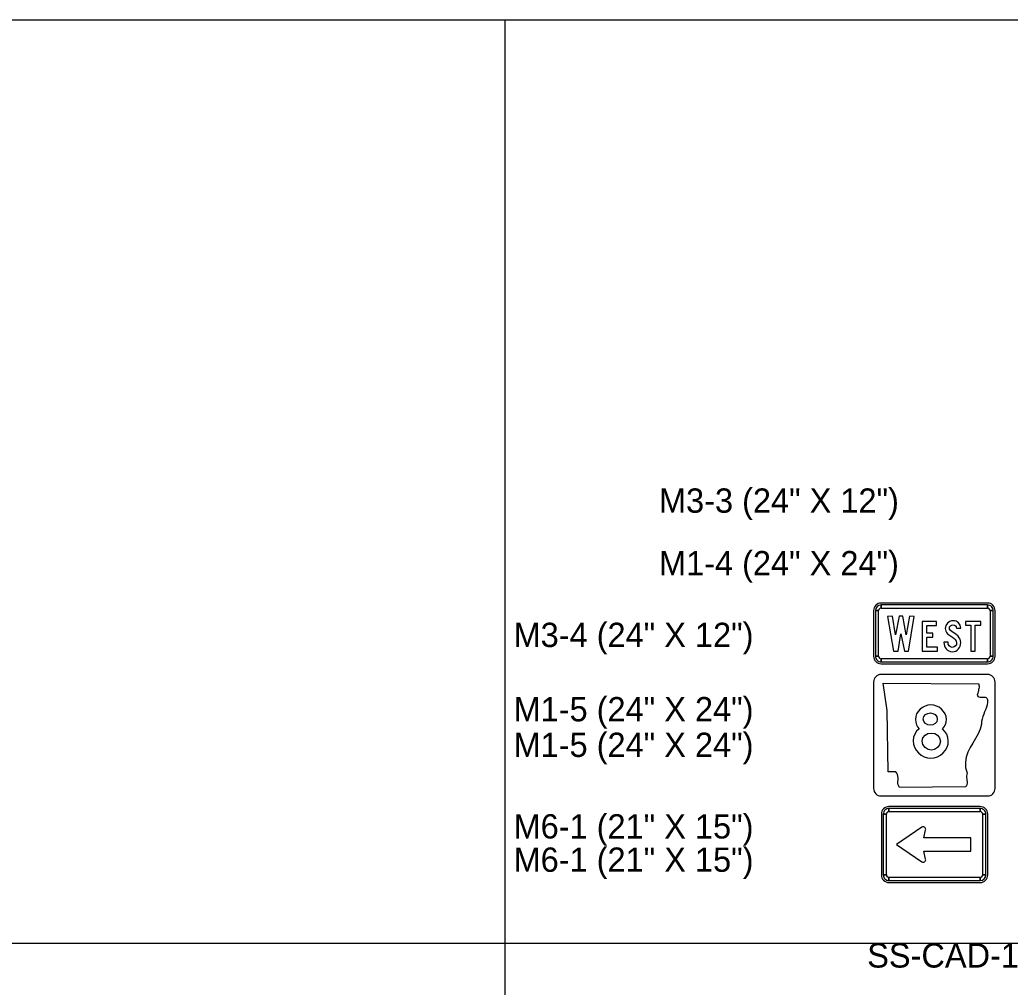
# Model space of a CAD drawing. Extents: x 1001568 to 1002149, y 1840825 to 1841423.
# Drawn here: x 1001912.67 to 1001928.96, y 1841194.75 to 1841210.67 of the extents above; entities that cross this region are included whole.
import ezdxf

# ---------------------------------------------------------------- set-up
doc = ezdxf.new("R2010")
doc.units = 0
for name, color, linetype in [('40', 7, 'Continuous'), ('R_No Plot', 7, 'Continuous'), ('SIGNS', 7, 'Continuous')]:
    doc.layers.add(name, color=color, linetype=linetype)

msp = doc.modelspace()

# ---------------------------------------------------------------- linework, layer by layer
at = {"layer": 'R_No Plot'}
for p, q in [((1001920.65, 1841210.667), (1001920.65, 1841148.127)), ((1001886.411, 1841195.469), (1001982.133, 1841195.469))]:
    msp.add_line(p, q, dxfattribs=at)
msp.add_lwpolyline([(1001886.411, 1841210.667), (1001964.232, 1841210.667), (1001964.232, 1841207.694), (1001968.454, 1841207.694), (1001968.454, 1841206.882), (1001982.133, 1841206.882), (1001982.133, 1841148.127), (1001886.411, 1841148.127)], close=True, dxfattribs=at)
at = {"layer": 'SIGNS'}
for p, q in [((1001928.589, 1841201.068), (1001926.839, 1841201.068)), ((1001926.839, 1841200.985), (1001926.839, 1841201.037)), ((1001928.589, 1841201.037), (1001928.589, 1841200.985)), ((1001926.714, 1841200.943), (1001926.714, 1841200.193)), ((1001926.745, 1841200.943), (1001926.797, 1841200.943)), ((1001928.631, 1841200.943), (1001928.683, 1841200.943)), ((1001928.714, 1841200.193), (1001928.714, 1841200.943)), ((1001926.797, 1841200.193), (1001926.745, 1841200.193)), ((1001928.683, 1841200.193), (1001928.631, 1841200.193)), ((1001926.839, 1841200.1), (1001926.839, 1841200.152)), ((1001926.839, 1841200.068), (1001928.589, 1841200.068)), ((1001928.589, 1841200.152), (1001928.589, 1841200.1)), ((1001928.589, 1841199.893), (1001926.839, 1841199.893)), ((1001926.714, 1841199.768), (1001926.714, 1841198.018)), ((1001928.714, 1841198.018), (1001928.714, 1841199.768)), ((1001926.714, 1841198.018), (1001926.714, 1841198.018)), ((1001926.839, 1841197.893), (1001928.589, 1841197.893)), ((1001926.843, 1841197.594), (1001926.843, 1841196.594)), ((1001926.874, 1841197.594), (1001926.926, 1841197.594)), ((1001928.468, 1841197.719), (1001926.968, 1841197.719)), ((1001926.968, 1841197.636), (1001926.968, 1841197.688)), ((1001928.468, 1841197.688), (1001928.468, 1841197.636)), ((1001928.509, 1841197.594), (1001928.562, 1841197.594)), ((1001928.593, 1841196.594), (1001928.593, 1841197.594)), ((1001927.508, 1841197.379), (1001927.093, 1841197.094)), ((1001927.541, 1841197.203), (1001927.571, 1841197.335)), ((1001928.312, 1841197.203), (1001927.541, 1841197.203)), ((1001928.312, 1841197.203), (1001928.312, 1841197.203)), ((1001928.312, 1841196.985), (1001928.312, 1841197.203)), ((1001927.093, 1841197.094), (1001927.093, 1841197.094)), ((1001927.093, 1841197.094), (1001927.508, 1841196.809)), ((1001927.571, 1841196.853), (1001927.541, 1841196.985)), ((1001927.541, 1841196.985), (1001928.312, 1841196.985)), ((1001926.926, 1841196.594), (1001926.874, 1841196.594)), ((1001926.968, 1841196.5), (1001926.968, 1841196.552)), ((1001926.968, 1841196.469), (1001928.468, 1841196.469)), ((1001928.468, 1841196.552), (1001928.468, 1841196.5)), ((1001928.562, 1841196.594), (1001928.509, 1841196.594))]:
    msp.add_line(p, q, dxfattribs=at)
for points in [[(1001928.589, 1841201.037), (1001926.839, 1841201.037), (1001926.839, 1841200.985), (1001928.589, 1841200.985), (1001928.589, 1841201.037), (1001928.589, 1841201.037)], [(1001926.745, 1841200.943), (1001926.745, 1841200.193), (1001926.797, 1841200.193), (1001926.797, 1841200.943), (1001926.745, 1841200.943), (1001926.745, 1841200.943)], [(1001927.041, 1841200.277), (1001927.118, 1841200.277), (1001927.164, 1841200.562), (1001927.221, 1841200.277), (1001927.291, 1841200.277), (1001927.384, 1841200.849), (1001927.304, 1841200.854), (1001927.253, 1841200.546), (1001927.197, 1841200.854), (1001927.133, 1841200.854), (1001927.076, 1841200.546), (1001927.027, 1841200.854), (1001926.946, 1841200.849)], [(1001928.683, 1841200.193), (1001928.683, 1841200.943), (1001928.631, 1841200.943), (1001928.631, 1841200.193), (1001928.683, 1841200.193), (1001928.683, 1841200.193)], [(1001927.768, 1841200.344), (1001927.588, 1841200.344), (1001927.588, 1841200.508), (1001927.69, 1841200.508), (1001927.69, 1841200.575), (1001927.588, 1841200.575), (1001927.588, 1841200.7), (1001927.75, 1841200.7), (1001927.75, 1841200.767), (1001927.516, 1841200.767), (1001927.516, 1841200.277), (1001927.768, 1841200.277)], [(1001927.872, 1841200.424), (1001927.872, 1841200.42), (1001927.874, 1841200.39), (1001927.881, 1841200.362), (1001927.893, 1841200.337), (1001927.91, 1841200.314), (1001927.931, 1841200.293), (1001927.955, 1841200.279), (1001927.981, 1841200.27), (1001928.01, 1841200.267), (1001928.04, 1841200.27), (1001928.066, 1841200.278), (1001928.09, 1841200.292), (1001928.111, 1841200.312), (1001928.127, 1841200.335), (1001928.139, 1841200.36), (1001928.146, 1841200.387), (1001928.148, 1841200.417), (1001928.146, 1841200.445), (1001928.137, 1841200.472), (1001928.123, 1841200.498), (1001928.104, 1841200.522), (1001928.067, 1841200.554), (1001928.01, 1841200.593), (1001927.973, 1841200.621), (1001927.965, 1841200.636), (1001927.962, 1841200.652), (1001927.966, 1841200.674), (1001927.98, 1841200.692), (1001927.999, 1841200.705), (1001928.021, 1841200.709), (1001928.046, 1841200.705), (1001928.063, 1841200.693), (1001928.073, 1841200.677), (1001928.08, 1841200.652), (1001928.148, 1841200.652), (1001928.137, 1841200.702), (1001928.111, 1841200.741), (1001928.092, 1841200.757), (1001928.071, 1841200.768), (1001928.046, 1841200.775), (1001928.019, 1841200.777), (1001927.994, 1841200.774), (1001927.971, 1841200.767), (1001927.95, 1841200.755), (1001927.931, 1841200.739), (1001927.903, 1841200.698), (1001927.894, 1841200.65), (1001927.896, 1841200.625), (1001927.903, 1841200.603), (1001927.915, 1841200.582), (1001927.931, 1841200.563), (1001928.011, 1841200.506), (1001928.041, 1841200.484), (1001928.059, 1841200.467), (1001928.075, 1841200.442), (1001928.081, 1841200.416), (1001928.076, 1841200.387), (1001928.062, 1841200.363), (1001928.039, 1841200.345), (1001928.01, 1841200.339), (1001927.98, 1841200.345), (1001927.957, 1841200.365), (1001927.943, 1841200.392), (1001927.939, 1841200.424)], [(1001928.316, 1841200.277), (1001928.388, 1841200.277), (1001928.388, 1841200.706), (1001928.479, 1841200.706), (1001928.479, 1841200.767), (1001928.227, 1841200.767), (1001928.227, 1841200.706), (1001928.316, 1841200.706)], [(1001926.839, 1841200.1), (1001928.589, 1841200.1), (1001928.589, 1841200.152), (1001926.839, 1841200.152), (1001926.839, 1841200.1), (1001926.839, 1841200.1)], [(1001928.444, 1841199.738), (1001928.448, 1841199.719), (1001928.45, 1841199.7), (1001928.449, 1841199.681), (1001928.447, 1841199.662), (1001928.443, 1841199.643), (1001928.438, 1841199.624), (1001928.433, 1841199.605), (1001928.427, 1841199.586), (1001928.422, 1841199.568), (1001928.417, 1841199.55), (1001928.431, 1841199.534), (1001928.448, 1841199.524), (1001928.468, 1841199.52), (1001928.489, 1841199.52), (1001928.511, 1841199.521), (1001928.531, 1841199.521), (1001928.55, 1841199.519), (1001928.567, 1841199.513), (1001928.58, 1841199.501), (1001928.588, 1841199.48), (1001928.589, 1841199.435), (1001928.583, 1841199.392), (1001928.572, 1841199.352), (1001928.558, 1841199.313), (1001928.542, 1841199.275), (1001928.526, 1841199.237), (1001928.511, 1841199.199), (1001928.499, 1841199.159), (1001928.491, 1841199.118), (1001928.489, 1841199.074), (1001928.467, 1841198.991), (1001928.433, 1841198.913), (1001928.392, 1841198.838), (1001928.348, 1841198.763), (1001928.305, 1841198.688), (1001928.267, 1841198.612), (1001928.239, 1841198.534), (1001928.225, 1841198.451), (1001928.228, 1841198.364), (1001928.254, 1841198.27), (1001928.246, 1841198.247), (1001928.244, 1841198.223), (1001928.244, 1841198.199), (1001928.247, 1841198.175), (1001928.251, 1841198.151), (1001928.253, 1841198.128), (1001928.254, 1841198.104), (1001928.251, 1841198.083), (1001928.242, 1841198.061), (1001928.227, 1841198.042), (1001927.143, 1841198.032), (1001927.129, 1841198.052), (1001927.12, 1841198.075), (1001927.116, 1841198.102), (1001927.116, 1841198.13), (1001927.117, 1841198.16), (1001927.117, 1841198.189), (1001927.115, 1841198.218), (1001927.109, 1841198.245), (1001927.098, 1841198.269), (1001927.08, 1841198.29), (1001926.954, 1841198.29), (1001926.936, 1841199.302), (1001926.872, 1841199.748), (1001928.444, 1841199.738), (1001928.444, 1841199.738)], [(1001926.874, 1841197.594), (1001926.874, 1841196.594), (1001926.926, 1841196.594), (1001926.926, 1841197.594), (1001926.874, 1841197.594), (1001926.874, 1841197.594)], [(1001928.468, 1841197.688), (1001926.968, 1841197.688), (1001926.968, 1841197.636), (1001928.468, 1841197.636), (1001928.468, 1841197.688), (1001928.468, 1841197.688)], [(1001928.562, 1841196.594), (1001928.562, 1841197.594), (1001928.509, 1841197.594), (1001928.509, 1841196.594), (1001928.562, 1841196.594), (1001928.562, 1841196.594)], [(1001926.968, 1841196.5), (1001928.468, 1841196.5), (1001928.468, 1841196.552), (1001926.968, 1841196.552), (1001926.968, 1841196.5), (1001926.968, 1841196.5)]]:
    msp.add_lwpolyline(points, close=True, dxfattribs=at)
for points in [[(1001926.839, 1841199.893), (1001926.839, 1841199.893)], [(1001928.589, 1841199.893), (1001928.589, 1841199.893)], [(1001926.714, 1841199.768), (1001926.714, 1841199.768)], [(1001927.847, 1841198.998), (1001927.875, 1841199.031), (1001927.896, 1841199.068), (1001927.908, 1841199.108), (1001927.912, 1841199.151), (1001927.907, 1841199.199), (1001927.892, 1841199.244), (1001927.867, 1841199.285), (1001927.833, 1841199.322), (1001927.793, 1841199.352), (1001927.751, 1841199.373), (1001927.705, 1841199.386), (1001927.656, 1841199.391), (1001927.608, 1841199.386), (1001927.562, 1841199.373), (1001927.519, 1841199.351), (1001927.48, 1841199.32), (1001927.446, 1841199.283), (1001927.422, 1841199.243), (1001927.407, 1841199.199), (1001927.403, 1841199.151), (1001927.407, 1841199.106), (1001927.419, 1841199.066), (1001927.439, 1841199.029), (1001927.467, 1841198.998), (1001927.423, 1841198.958), (1001927.392, 1841198.912), (1001927.373, 1841198.86), (1001927.367, 1841198.803), (1001927.372, 1841198.746), (1001927.389, 1841198.694), (1001927.416, 1841198.646), (1001927.453, 1841198.601), (1001927.499, 1841198.564), (1001927.547, 1841198.537), (1001927.6, 1841198.521), (1001927.656, 1841198.516), (1001927.712, 1841198.521), (1001927.765, 1841198.537), (1001927.813, 1841198.564), (1001927.858, 1841198.601), (1001927.896, 1841198.646), (1001927.923, 1841198.694), (1001927.939, 1841198.746), (1001927.944, 1841198.803), (1001927.938, 1841198.858), (1001927.92, 1841198.909), (1001927.889, 1841198.956), (1001927.847, 1841198.998)], [(1001927.763, 1841199.155), (1001927.754, 1841199.115), (1001927.725, 1841199.084), (1001927.689, 1841199.066), (1001927.649, 1841199.061), (1001927.608, 1841199.066), (1001927.571, 1841199.085), (1001927.542, 1841199.117), (1001927.532, 1841199.158), (1001927.542, 1841199.199), (1001927.571, 1841199.232), (1001927.608, 1841199.252), (1001927.649, 1841199.259), (1001927.691, 1841199.252), (1001927.727, 1841199.232), (1001927.754, 1841199.198), (1001927.763, 1841199.155)], [(1001927.813, 1841198.794), (1001927.801, 1841198.737), (1001927.768, 1841198.69), (1001927.719, 1841198.658), (1001927.665, 1841198.648), (1001927.611, 1841198.658), (1001927.563, 1841198.69), (1001927.527, 1841198.738), (1001927.516, 1841198.794), (1001927.527, 1841198.849), (1001927.563, 1841198.893), (1001927.609, 1841198.919), (1001927.665, 1841198.928), (1001927.72, 1841198.919), (1001927.766, 1841198.893), (1001927.801, 1841198.849), (1001927.813, 1841198.794)], [(1001926.839, 1841197.893), (1001926.839, 1841197.893)], [(1001928.589, 1841197.893), (1001928.589, 1841197.893)]]:
    msp.add_lwpolyline(points, dxfattribs=at)
for centre, radius, start, end in [((1001926.839, 1841200.943), 0.125, 90.0002, 179.9998), ((1001926.839, 1841200.943), 0.0937, 90.0002, 179.9998), ((1001928.589, 1841200.943), 0.125, 0, 90.0002), ((1001928.589, 1841200.943), 0.0937, 0, 90.0002), ((1001926.839, 1841200.943), 0.0417, 90.0002, 179.9998), ((1001928.589, 1841200.943), 0.0417, 0, 90.0002), ((1001926.839, 1841200.193), 0.125, 179.9998, 270.0001), ((1001926.839, 1841200.193), 0.0937, 179.9998, 270.0001), ((1001926.839, 1841200.193), 0.0417, 179.9998, 270.0001), ((1001928.589, 1841200.193), 0.125, 270.0001, 0.0003), ((1001928.589, 1841200.193), 0.0937, 270.0001, 0.0003), ((1001928.589, 1841200.193), 0.0417, 270.0001, 0.0003), ((1001926.839, 1841199.768), 0.125, 90.0002, 179.9998), ((1001928.589, 1841199.768), 0.125, 0, 90), ((1001926.839, 1841198.018), 0.125, 180, 270), ((1001928.589, 1841198.018), 0.125, 270.0001, 0.0003), ((1001926.968, 1841197.594), 0.125, 90.0001, 180.0003), ((1001926.968, 1841197.594), 0.0937, 90.0001, 180.0003), ((1001926.968, 1841197.594), 0.0417, 90.0001, 180.0003), ((1001928.468, 1841197.594), 0.125, 359.9998, 90.0001), ((1001928.468, 1841197.594), 0.0937, 359.9998, 90.0001), ((1001928.468, 1841197.594), 0.0417, 359.9998, 90.0001), ((1001927.53, 1841197.344), 0.0417, 347.0499, 122.2759), ((1001927.53, 1841196.844), 0.0417, 237.7244, 12.9504), ((1001926.968, 1841196.594), 0.125, 180, 270.0002), ((1001926.968, 1841196.594), 0.0937, 180, 270.0002), ((1001926.968, 1841196.594), 0.0417, 180, 270.0002), ((1001928.468, 1841196.594), 0.0937, 270.0002, 359.9998), ((1001928.468, 1841196.594), 0.0417, 270.0002, 359.9998), ((1001928.468, 1841196.594), 0.125, 270.0002, 359.9998)]:
    msp.add_arc(centre, radius, start, end, dxfattribs=at)

# ---------------------------------------------------------------- texts
at = {"layer": '40'}
for s, p in [('M3-3 (24" X 12")', (1001923.184, 1841202.554)), ('M1-4 (24" X 24")', (1001923.184, 1841201.524)), ('M3-4 (24" X 12")', (1001920.792, 1841200.344)), ('M1-5 (24" X 24")', (1001920.792, 1841199.121)), ('M1-5 (24" X 24")', (1001920.792, 1841198.535)), ('M6-1 (21" X 15")', (1001920.792, 1841197.193)), ('M6-1 (21" X 15")', (1001920.792, 1841196.645)), ('SS-CAD-10-STA51+75WB', (1001926.61, 1841195.069))]:
    msp.add_text(s, height=0.4, rotation=0, dxfattribs=at).set_placement(p)

doc.saveas('drawing.dxf')
